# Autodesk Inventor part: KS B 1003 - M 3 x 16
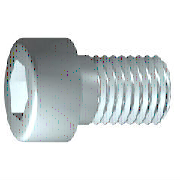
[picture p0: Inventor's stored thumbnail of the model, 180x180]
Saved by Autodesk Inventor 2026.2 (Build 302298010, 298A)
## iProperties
Created: 2025-01
Part Number: KS B 1003 - M 3 x 16
Material: 강철, 연강
Description: 6각머리 태핑 나사
Document SubType Name: Modeling
Standard: KS B 1003
Designer: work
Standards Organization: KS
Language: ko-KR
Size Designation: M 3 x 16
Categories: <MemberInstance><Categories><Category DisplayName="조임쇠" InternalName="e4da775c-781d-43d5-af7c-5136215cf5a6" Mnemonic="FSTN"><Category DisplayName="볼트" InternalN
Density: 7.85 g/cm^3
Appearance: 반연마
IsCustomPart: 1
Author: work
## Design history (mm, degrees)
body "Solid1"
workplane "Work Plane1"
fillet "Fillet2" dims "d30" = 0.1 (= R)
revolve "본체" stored, may be unused: angle "d10" = 90 deg
sketch "스케치2"
  geometry: L1 (0, -3.85)-(0, 3.85) reference; L2 (-3.85, 0)-(3.85, 0) reference; L3 (1.443, 0)-(0.722, -1.25); L4 (0.722, -1.25)-(-0.722, -1.25); L5 (-0.722, -1.25)-(-1.443, 0); L6 (-1.443, 0)-(-0.722, 1.25); L7 (-0.722, 1.25)-(0.722, 1.25); L8 (0.722, 1.25)-(1.443, 0); 2 further points
  constraints: 12 end point, 1 coincident, 1 horizontal alignment, 1 point on line, 12 other
extrude "슬롯" join sketch "스케치2" stored distance "d11" = 10; taper "d12" = 0 deg
fillet "모깎기1" dims "d17" = 0.3 (= RR)
feature "스레드" dims "d13" = 14.75 (= GEL), "d14" = 0
chamfer "모따기1" distance "d15" = 0.30673 (= -0.5 x SPD + 0.5 x GD); stored, may be unused: second distance "d16" = 0.30673 (= GUL), angle "d27" = 45 deg
sketch "스케치1"
  geometry: L1 (-0.867, 0)-(16, 0); L2 (16, 0)-(16, 1.5); L3 (16, 1.5)-(1.25, 1.5); L4 (1.25, 1.5)-(0.943, 1.5); L5 (0.943, 1.5)-(0, 1.5); L6 (0, 1.5)-(0, 2.75); L7 (0, 2.75)-(-3, 2.75); L8 (-3, 2.75)-(-3, 1.443); L9 (-3, 1.443)-(-1.7, 1.443); L10 (-1.7, 1.443)-(-0.867, 0); L11 (-6.8, 0)-(19.8, 0) reference; L12 (0, -0.55)-(0, 3.3) reference; L13 (1.25, 1.5)-(0, 1.5)
  constraints: 22 end point, 6 parallel, 2 collinear, 2 perpendicular, 1 horizontal, 1 point on line
  dimensions: "d1" = 14.75 distance from line of L3.end L2 (= GEL); "d2" = 0.30683 distance of L4.end L3.end (computed from GAL); "d3" = 3 distance between parallel lines of L8 L6 (= KOH); "d4" = 1.3 distance of L8.end L9.end (= INTI); "d5" = 60 deg angle of L10 L1; "d6" = 3 diameter of L3 L1 (= GD); "d7" = 3 diameter of L5 L1 (= BDM); "d8" = 2.88675 diameter of L9 L1 (= 1.1547 x SW); "d9" = 5.5 diameter of L7 L1 (= KOD); "d26" = 16 distance between parallel lines of L12 L2 (= NLG)
other parameters: "GD" = 3 (= NND) [user parameter; used in 2 equation terms], "NLG" = 16 [user parameter; used in 1 equation term], "GEL" = 14.75 [user parameter; used in 2 equation terms], "KOD" = 5.5 [user parameter; used in 1 equation term], "KOH" = 3 [user parameter; used in 1 equation term], "INTI" = 1.3 [user parameter; used in 1 equation term], "GAL" = 0.30673 (= 0.61345 x PTC) [user parameter; used in 1 equation term], "GUL" = 0.30673 (= 0.61345 x PTC) [user parameter; used in 1 equation term], "BDM" = 3 (= NND) [user parameter; used in 1 equation term], "SW" = 2.5 [user parameter; used in 2 equation terms], "RR" = 0.3 [user parameter; used in 1 equation term], "SPD" = 2.38655 (= NND - 1.2269 x PTC) [user parameter; used in 1 equation term], "d19" = 0, "d28" = 0, "d29" = 0, "R" = 0.1 [user parameter; used in 1 equation term], "PHH" = 0.1 [user parameter], "GD1" = 2.38655 (= THREADDIA - 1.2269 x PTC) [user parameter], "THREADDIA" = 3 [user parameter; used in 1 equation term], "FAWI" = 45 deg [user parameter], "PTC" = 0.5 [user parameter; used in 5 equation terms], "NND" = 3 [user parameter; used in 3 equation terms], "TOA" = 30 deg [user parameter], "E0" = 2.8875 (= 1.155 x SW) [user parameter]
